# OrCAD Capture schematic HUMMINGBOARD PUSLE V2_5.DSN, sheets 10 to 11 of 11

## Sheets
10 MIPI-DSI to HDMI: size C; title: MIPI-DSI to HDMI; rev: 2.4.0
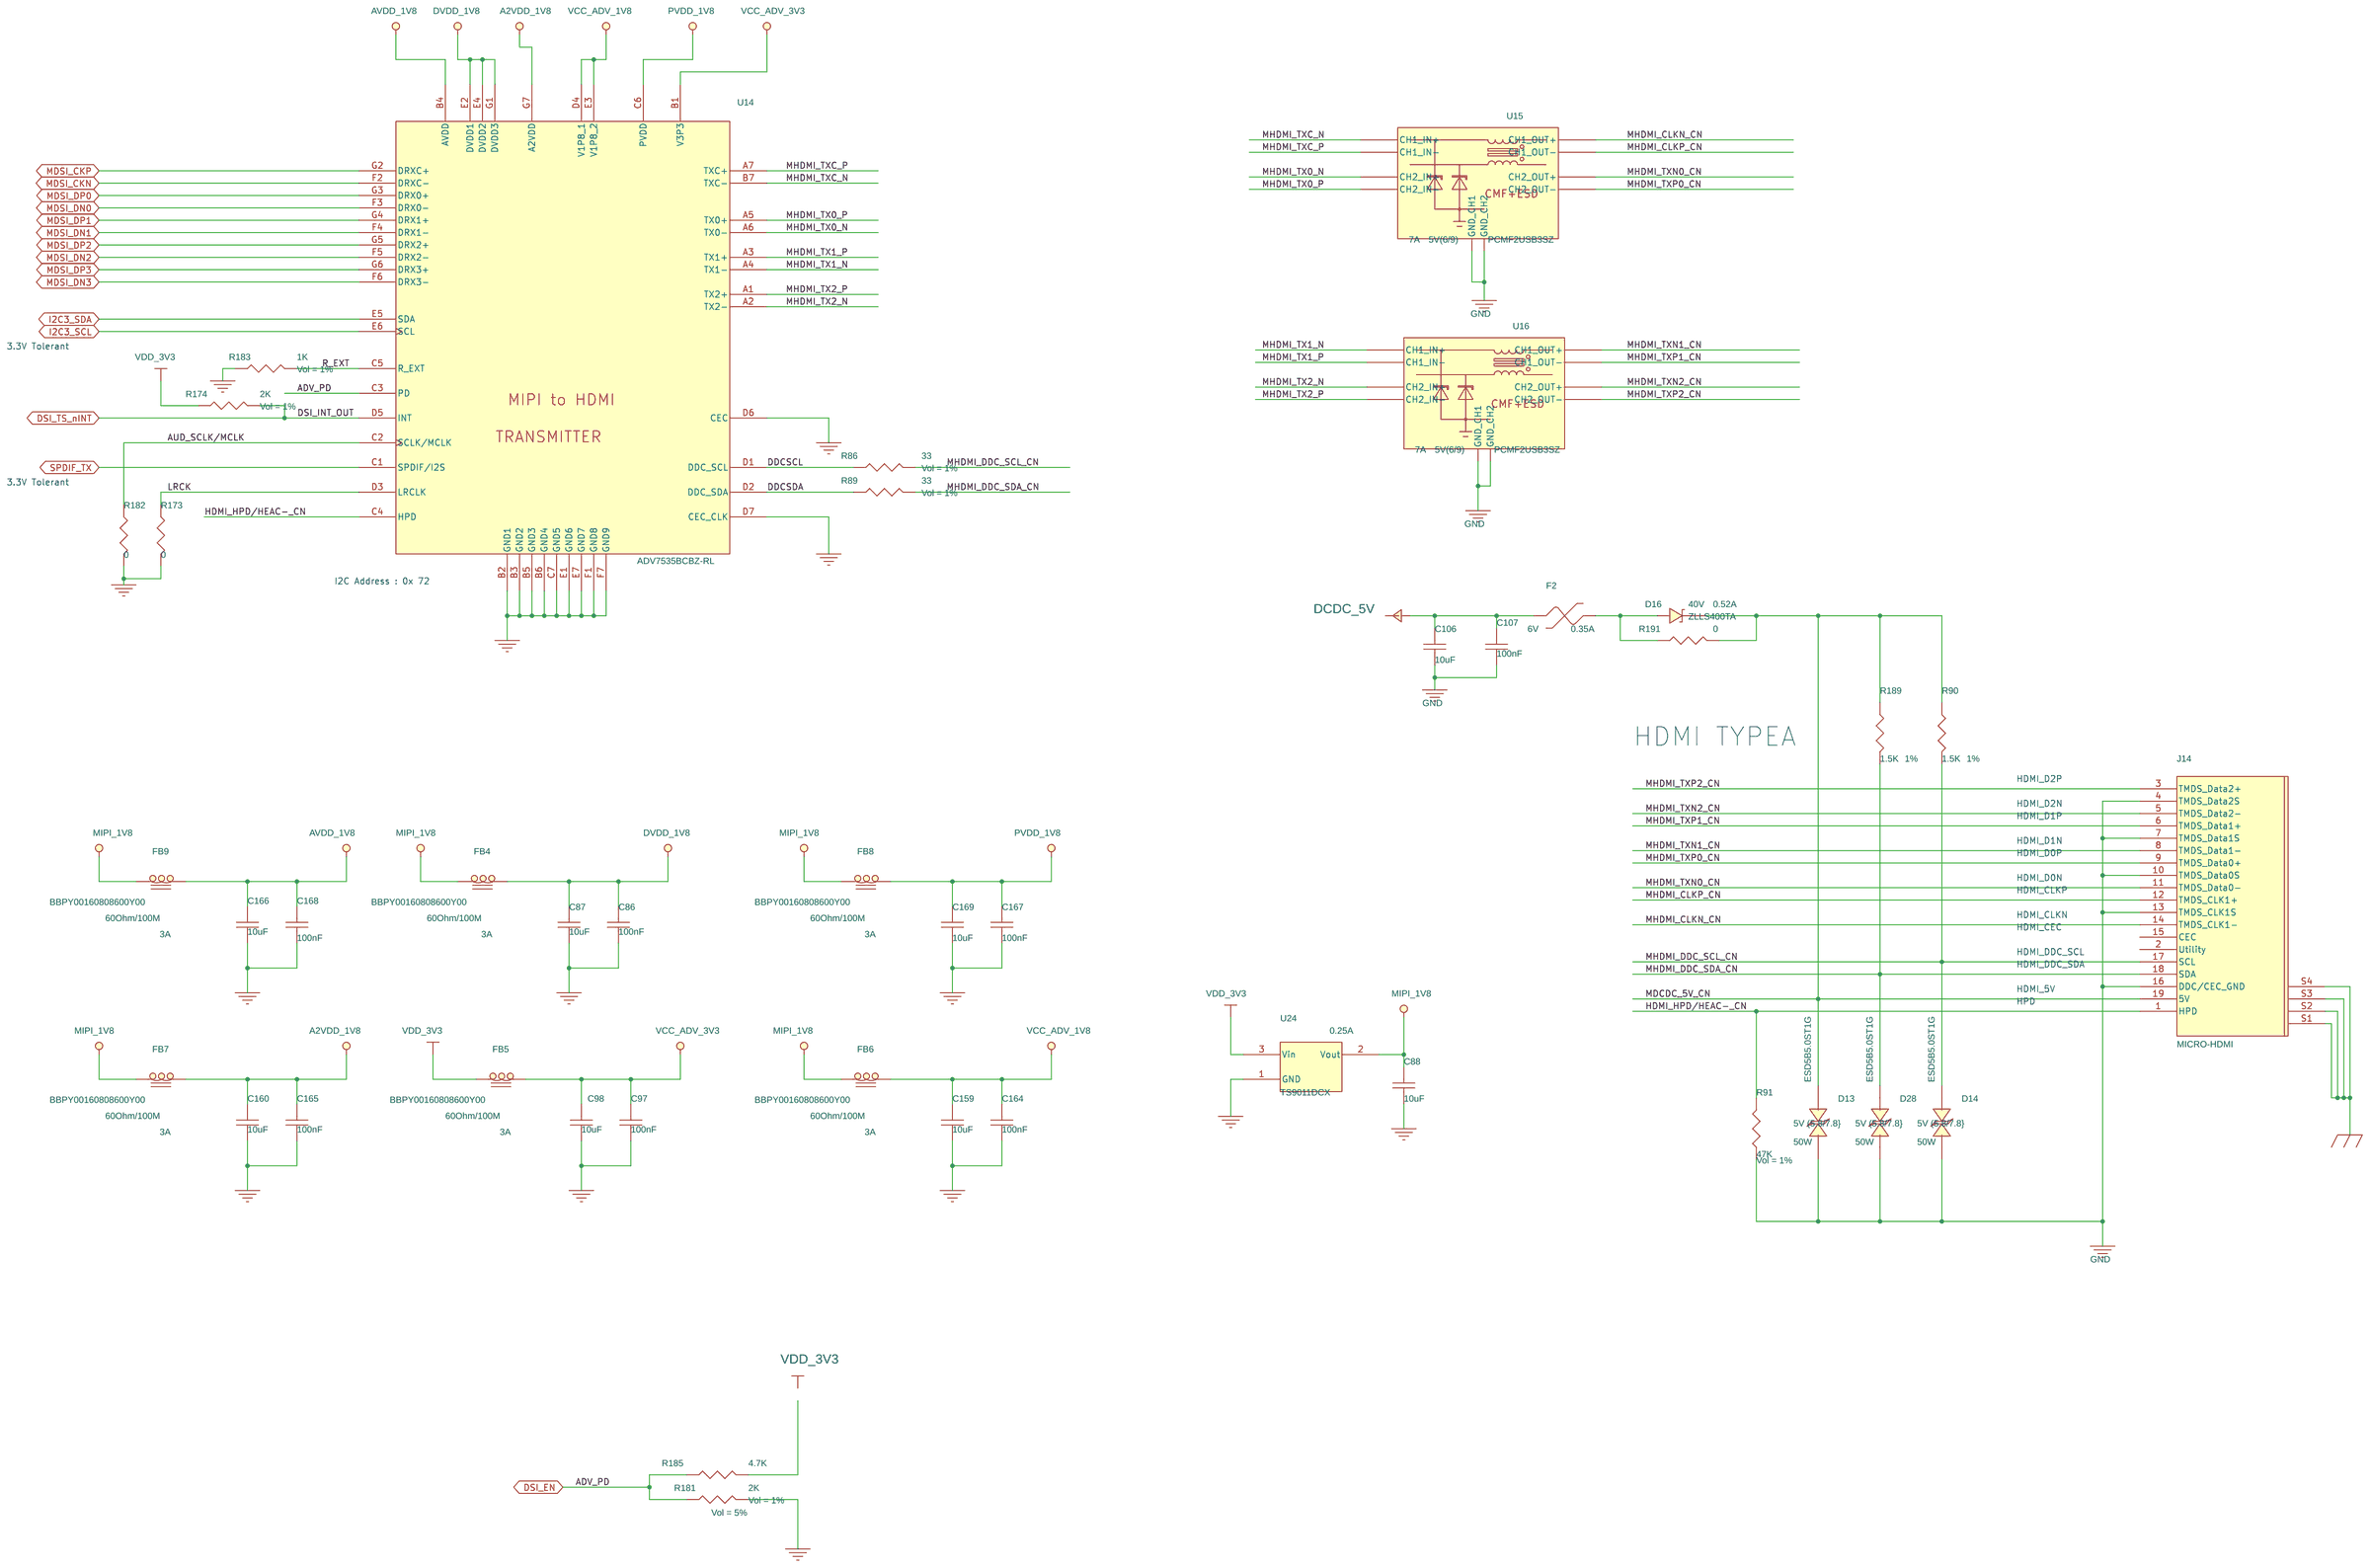
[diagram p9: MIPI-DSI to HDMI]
11 History: title: HISTORY
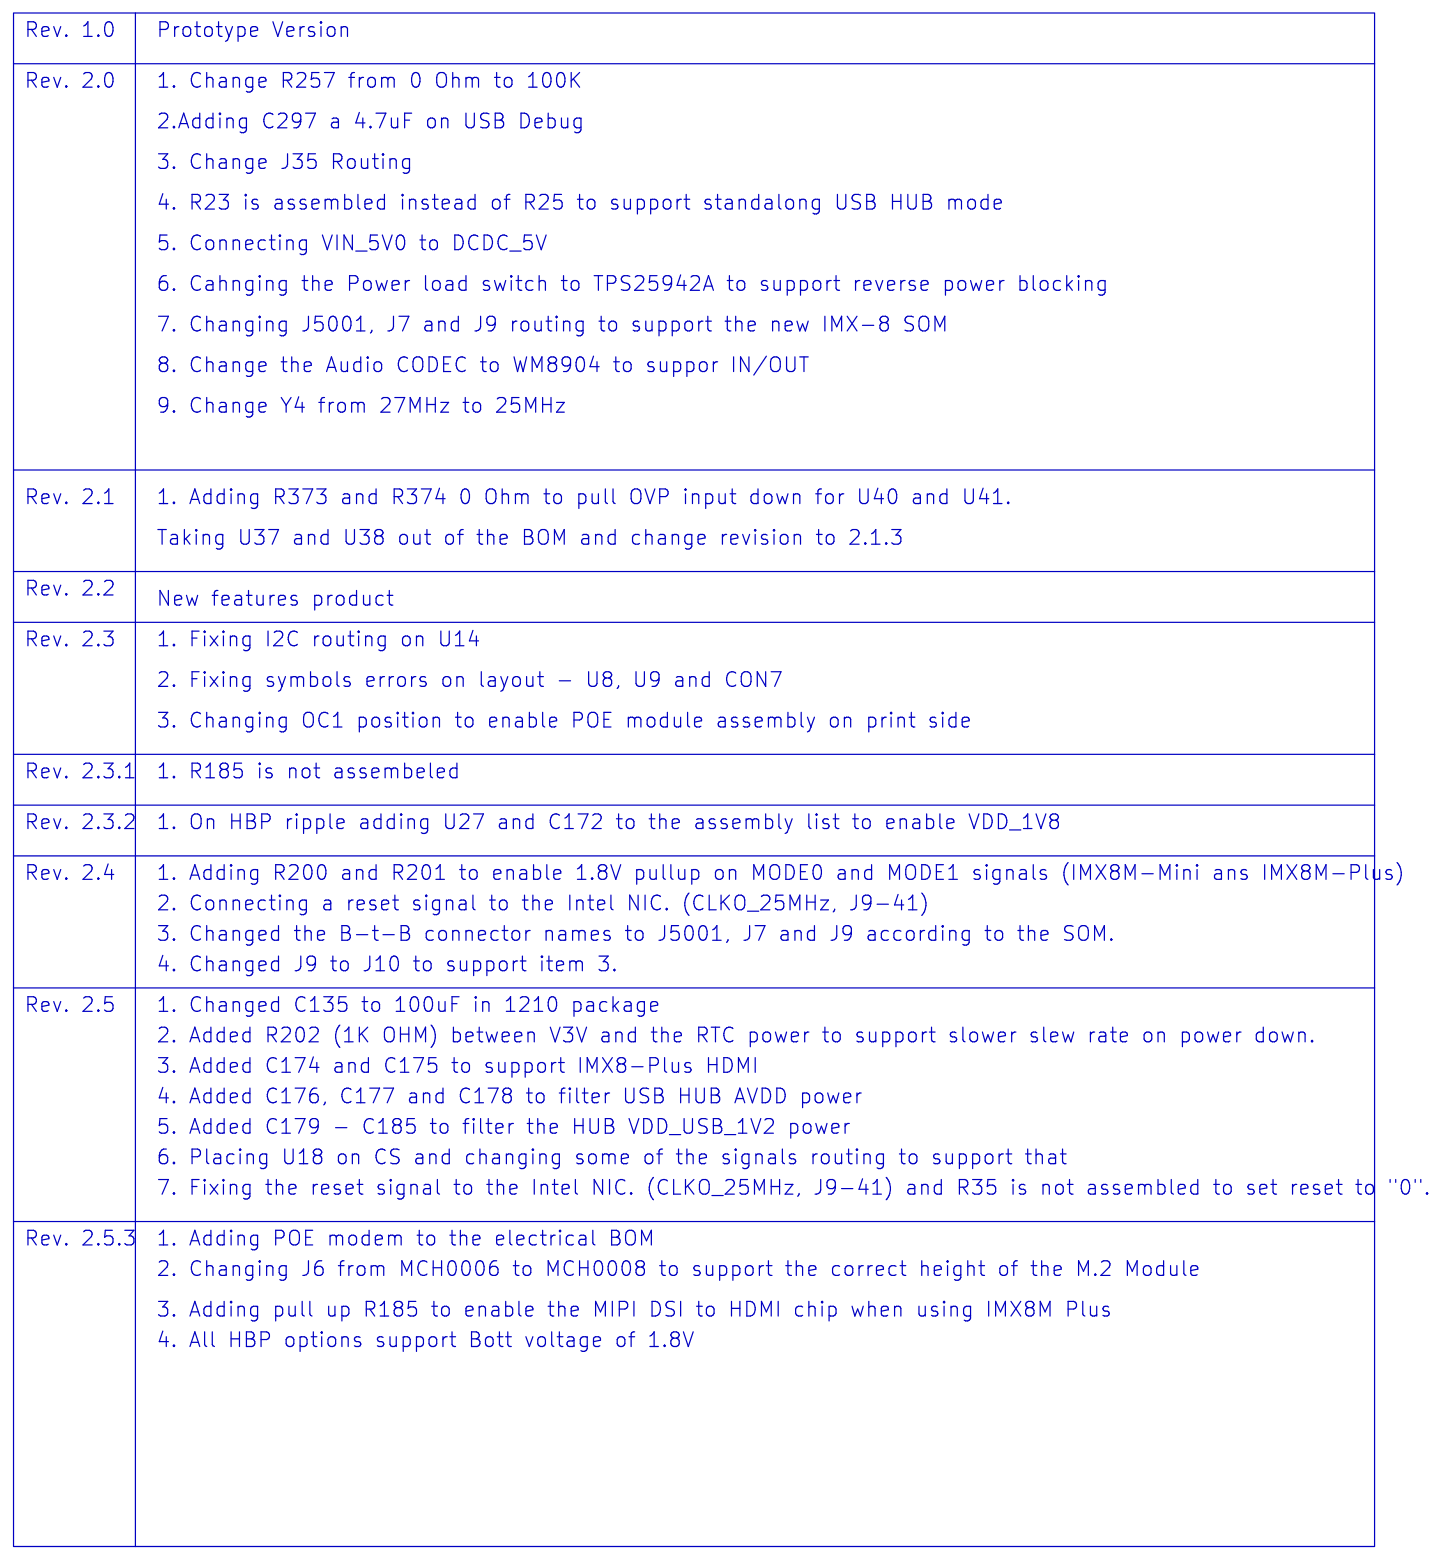
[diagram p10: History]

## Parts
C86  100nF  [C0402]
C87  10uF  [C0603]
C88  10uF  [C0603]
C97  100nF  [C0402]
C98  10uF  [C0603]
C106  10uF  [C0603]
C107  100nF  [C0402]
C159  10uF  [C0603]
C160  10uF  [C0603]
C164  100nF  [C0402]
C165  100nF  [C0402]
C166  10uF  [C0603]
C167  100nF  [C0402]
C168  100nF  [C0402]
C169  10uF  [C0603]
D13  ESD5B5.0ST1G  [ESD5B5.0ST1G]
D14  ESD5B5.0ST1G  [ESD5B5.0ST1G]
D16  ZLLS400TA  [ZLLS400TA]
D28  ESD5B5.0ST1G  [ESD5B5.0ST1G]
F2  6V  [PICOSMDC035S-2]
FB4  BBPY00160808600Y00  [BBPY00160808600Y00]
FB5  BBPY00160808600Y00  [BBPY00160808600Y00]
FB6  BBPY00160808600Y00  [BBPY00160808600Y00]
FB7  BBPY00160808600Y00  [BBPY00160808600Y00]
FB8  BBPY00160808600Y00  [BBPY00160808600Y00]
FB9  BBPY00160808600Y00  [BBPY00160808600Y00]
J14  MICRO-HDMI  [0467651001]
R86  33  [R0402]
R89  33  [R0402]
R90  1.5K  [R0402]
R91  47K  [R0402]
R173  0  [R0402]
R174  2K  [R0402]
R181  2K  [R0402]
R182  0  [R0402]
R183  1K  [R0402]
R185  4.7K  [R0402]
R189  1.5K  [R0402]
R191  0  [R0402]
U14  ADV7535BCBZ-RL  [ADV7535BCBZ-RL]
U15  PCMF2USB3SZ  [PCMF2USB3SZ]
U16  PCMF2USB3SZ  [PCMF2USB3SZ]
U24  TS9011DCX  [TS9011DCX]

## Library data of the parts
C86 C97 C164 C165 C167 C168 = CAP_NP1: CAP CER 0.1uF ±10% 16V X7R 0402; Category: Capacitors (Size: 0402); Digikey P/N: 1276-1001-1-ND; Manufacturer: Samsung Electro-Mechanics; Part Num#: CL05B104KO5NNNC; Rating: 16V; SolidRun P/N: CA20013; Vol: 10%
C87 C98 C106 C159 C160 C166 C169 = CAP_NP1: CAP CER 10uF ±10% 16V X5R 0603; Category: Capacitors (Size: 0603); Digikey P/N: 490-10728-2-ND; Manufacturer: Murata Electronics North America; Part Num#: GRM188R61C106KAALD; Rating: 16V; SolidRun P/N: CA30014; Vol: 10%
C88 = CAP_NP1: CAP CER 10uF ±10% 6.3V X5R 0603; Category : Capacitors (Size: 0603); Digikey P/N: 1276-1038-1-ND; Manufacturer: Samsung Electro-Mechanics; Part Num#: CL10A106KQ8NNNC; Rating: 6.3V; SolidRun P/N: CA30001; Vol: 10%
C107 = CAP_NP1: CAP CER 0.1uF ±10% 16V X7R 0402; Category: Capacitors (Size: 0402); Category : Capacitors (Size: 0402); Digikey P/N: 1276-1001-1-ND; Manufacturer: Samsung Electro-Mechanics; Part Num#: CL05B104KO5NNNC; Rating: 16V; SolidRun P/N: CA20013; Vol: 10%
D13 D14 D28 = TVS-BI: TVS DIODE 5VWM SOD523 BI; Category: DI-TVS; Category : DI-TVS; Digikey P/N: ESD5B5.0ST1GOSTR-ND; Manufacturer: ON Semiconductor; Rating: 50W; SolidRun P/N: DI00242; Vol: 5V (5.8/7.8}; Datasheet: http://www.onsemi.com/pub/Collateral/ESD5B5.0ST1-D.PDF
D16 = Diode-STK: DIODE SCHOTTKY 40V 520MA SOD323; Category: DI-Diode; Digikey P/N: ZLLS400TATR-ND; Manufacturer: Diodes Incorporated; Rating: 0.52A; SolidRun P/N: DI00234; Vol: 40V; Datasheet: https://www.diodes.com/assets/Datasheets/ZLLS400.pdf
F2 = FUSE_RESETTABLE: PTC RESET FUSE 6V 350MA 0805; Category: Fuse-PTC; Category : Fuse-PTC; Digikey P/N: PICOSMDC035S-2TR-ND; Manufacturer: Littelfuse Inc.; Rating: 0.35A; SolidRun P/N: FS00020; Datasheet: http://www.littelfuse.com/~/media/electronics/product_specifications/resettable_ptcs/littelfuse_ptc_picosmdc035s_2_product_specification.pdf.pdf
FB4-FB9 = Ferrite_Bead: Multilayer Ferrite Chip Beads 60 OHM 3A; Category: COILS-FERRIT; Manufacturer: Chilisin Electronics Corp; Rating: 3A; SolidRun P/N: IN00049; Vol: 60Ohm/100M; Datasheet: https://www.chilisin.com/upload/media/product/emi/file/BBPY_Series.pdf
J14 = J-Micro_HDMI_connector: HDMI - Micro  Receptacle Connector 19 Position Surface Mount, Right Angle; Through Hole; Category: CON-HDMI/DP; Digikey P/N: WM1282TR-ND; Manufacturer: Molex; SolidRun P/N: CO00747; Datasheet: https://www.molex.com/pdm_docs/sd/467651001_sd.pdf
R86 R89 = RES1: RES SMD 33 OHM 1% 1/16W 0402; Category: Resistors (Size: 0402); Digikey P/N: 311-33.0LRCT-ND; Manufacturer: YAGEO; Part Num#: RC0402FR-0733RL; Rating: 1/16W; SolidRun P/N: RE20502; Vol: 1%
R90 R189 = RES1: RES SMD 1.5K OHM 1% 1/16W 0402; Category: Resistors (Size: 0402); Category : Resistors (Size: 0402); Manufacturer: THYE MING; Part Num#: CR-02FL6---1K5; Rating: 1/16W; SolidRun P/N: RE20029; Vol: 1%
R91 = RES1: RES SMD 47K OHM 1% 1/16W 0402; Category: Resistors (Size: 0402); Digikey P/N: 311-47.0KLRCT-ND; Manufacturer: YAGEO; Part Num#: RC0402FR-0747KL; Rating: 1/16W; SolidRun P/N: RE20469; Vol: 1%
R173 R182 = RES1: RES SMD 0 OHM JUMPER 1/16W 0402; Category: Resistors (Size: 0402); Digikey P/N: 311-0.0JRCT-ND; Manufacturer: YAGEO; Part Num#: RC0402JR-070RL; Rating: 1/16W; SolidRun P/N: RE20009
R174 R181 = RES1: RES SMD 2K OHM 1% 1/10W 0402; Category: Resistors (Size: 0402); Digikey P/N: P2.00KLTR-ND; Manufacturer: Panasonic Electronic Components; Part Num#: ERJ-2RKF2001X; Rating: 1/10W; SolidRun P/N: RE20524; Vol: 1%
R183 = RES1: RES SMD 1K OHM 1% 1/16W 0402; Category: Resistors (Size: 0402); Digikey P/N: 311-1.00KLRCT-ND; Manufacturer: YAGEO; Part Num#: RC0402FR-071KL; Rating: 1/16W; SolidRun P/N: RE20500; Vol: 1%
R185 = RES1: RES SMD 4.7K OHM 5% 1/16W 0402; Category: Resistors (Size: 0402); Digikey P/N: 311-4.7KJRCT-ND; Manufacturer: YAGEO; Part Num#: RC0402JR-074K7L; Rating: 1/16W; SolidRun P/N: RE20002; Vol: 5%
R191 = RES1: RES SMD 0 OHM JUMPER 1/16W 0402; Category: Resistors (Size: 0402); Category : Resistors (Size: 0402); Digikey P/N: 311-0.0JRCT-ND; Manufacturer: YAGEO; Part Num#: RC0402JR-070RL; Rating: 1/16W; SolidRun P/N: RE20009
U14 = IC-ADV7535BCBZ: MIPI/DSI Receiver with HDMI Transmitter; Category: IC-HDMI/LVDS; Manufacturer: Analog Devices Inc.; SolidRun P/N: IC01367
U15 U16 = D-PCMF2USB3S: CMC 4LN SMD ESD USB 3.1, USB 2.0, HDMI 2.0, HDMI 1.4; Category: DI-TVS; Category : DI-TVS; Digikey P/N: 1727-2509-2-ND; Manufacturer: Nexperia USA Inc.; Rating: 7A; SolidRun P/N: DI00240; Vol: 5V(6/9); Datasheet: https://assets.nexperia.com/documents/data-sheet/PCMFXUSB3S_SER.pdf
U24 = IC-TS9011DCX: LDO - 1.8V output, 0.25A, 12V maximum in; Category : IC-PWR-LDO; Digikey P/N: TS9011DCXRFG-ND; Manufacturer: Taiwan Semiconductor Corporation; Rating: 0.25A; SolidRun P/N: IC00014; VOL: 1.8V; Datasheet: http://www.taiwansemi.com/products/datasheet/TS9011_H1608.pdf

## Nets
A2VDD_1V8: C160.1 C165.1 FB7.2 U14.G7(A2VDD)
AVDD_1V8: C166.1 C168.1 FB9.2 U14.B4(AVDD)
DVDD_1V8: C86.1 C87.1 FB4.2 U14.E2(DVDD1) U14.E4(DVDD2) U14.G1(DVDD3)
GND: C86.2 C87.2 C88.2 C97.2 C98.2 C106.2 C107.2 C159.2 C160.2 C164.2 C165.2 C166.2 C167.2 C168.2 C169.2 D13.1 D14.1 D28.1 J14.4(TMDS_Data2S) J14.7(TMDS_Data1S) J14.10(TMDS_Data0S) J14.13(TMDS_CLK1S) J14.16(DDC/CEC_GND) R91.2 R173.2 R181.2 R182.2 R183.1 U14.B2(GND1) U14.B3(GND2) U14.B5(GND3) U14.B6(GND4) U14.C7(GND5) U14.D6(CEC) U14.D7(CEC_CLK) U14.E1(GND6) U14.E7(GND7) U14.F1(GND8) U14.F7(GND9) U15.B1(GND_CH1) U15.B2(GND_CH2) U16.B1(GND_CH1) U16.B2(GND_CH2) U24.1(GND) ; also on sheet 1 2 3 4 5 6 7 8 9
GNDC: J14.S1 J14.S2 J14.S3 J14.S4 ; also on sheet 1 4 5 7 8
PVDD_1V8: C167.1 C169.1 FB8.2 U14.C6(PVDD)
VCC_ADV_1V8: C159.1 C164.1 FB6.2 U14.D4(V1P8_1) U14.E3(V1P8_2)
VCC_ADV_3V3: C97.1 C98.1 FB5.2 U14.B1(V3P3)
VDD_3V3: FB5.1 R174.1 R185.2 U24.3(Vin) ; also on sheet 2 3 4 5 6 7 8 9
AUD_SCLK/MCLK: R182.1 U14.C2(SCLK/MCLK)
DCDC_5V: C106.1 C107.1 F2.1 ; also on sheet 1 2 4 5 8 9
DDCSCL: R86.1 U14.D1(DDC_SCL)
DDCSDA: R89.1 U14.D2(DDC_SDA)
DSI_EN: R181.1 R185.1 U14.C3(PD) ; also on sheet 8 9
DSI_TS_nINT: R174.2 U14.D5(INT) ; also on sheet 8 9
HDMI_HPD/HEAC-_CN: J14.1(HPD) R91.1 U14.C4(HPD)
I2C3_SCL: U14.E6(SCL) ; also on sheet 2 3 7 8 9
I2C3_SDA: U14.E5(SDA) ; also on sheet 2 3 7 8 9
LRCK: R173.1 U14.D3(LRCLK)
MDCDC_5V_CN: D13.2 D16.C(CATHODE) J14.19(5V) R90.1 R189.1 R191.2
MDSI_CKN: U14.F2(DRXC-) ; also on sheet 8
MDSI_CKP: U14.G2(DRXC+) ; also on sheet 8
MDSI_DN0: U14.F3(DRX0-) ; also on sheet 8
MDSI_DN1: U14.F4(DRX1-) ; also on sheet 8
MDSI_DN2: U14.F5(DRX2-) ; also on sheet 8
MDSI_DN3: U14.F6(DRX3-) ; also on sheet 8
MDSI_DP0: U14.G3(DRX0+) ; also on sheet 8
MDSI_DP1: U14.G4(DRX1+) ; also on sheet 8
MDSI_DP2: U14.G5(DRX2+) ; also on sheet 8
MDSI_DP3: U14.G6(DRX3+) ; also on sheet 8
MHDMI_CLKN_CN: J14.14(TMDS_CLK1-) U15.C1(CH1_OUT+)
MHDMI_CLKP_CN: J14.12(TMDS_CLK1+) U15.C2(CH1_OUT-)
MHDMI_DDC_SCL_CN: D14.2 J14.17(SCL) R86.2 R90.2
MHDMI_DDC_SDA_CN: D28.2 J14.18(SDA) R89.2 R189.2
MHDMI_TX0_N: U14.A6(TX0-) U15.A3(CH2_IN+)
MHDMI_TX0_P: U14.A5(TX0+) U15.A4(CH2_IN-)
MHDMI_TX1_N: U14.A4(TX1-) U16.A1(CH1_IN+)
MHDMI_TX1_P: U14.A3(TX1+) U16.A2(CH1_IN-)
MHDMI_TX2_N: U14.A2(TX2-) U16.A3(CH2_IN+)
MHDMI_TX2_P: U14.A1(TX2+) U16.A4(CH2_IN-)
MHDMI_TXC_N: U14.B7(TXC-) U15.A1(CH1_IN+)
MHDMI_TXC_P: U14.A7(TXC+) U15.A2(CH1_IN-)
MHDMI_TXN0_CN: J14.11(TMDS_Data0-) U15.C3(CH2_OUT+)
MHDMI_TXN1_CN: J14.8(TMDS_Data1-) U16.C1(CH1_OUT+)
MHDMI_TXN2_CN: J14.5(TMDS_Data2-) U16.C3(CH2_OUT+)
MHDMI_TXP0_CN: J14.9(TMDS_Data0+) U15.C4(CH2_OUT-)
MHDMI_TXP1_CN: J14.6(TMDS_Data1+) U16.C2(CH1_OUT-)
MHDMI_TXP2_CN: J14.3(TMDS_Data2+) U16.C4(CH2_OUT-)
MIPI_1V8: C88.1 FB4.1 FB6.1 FB7.1 FB8.1 FB9.1 U24.2(Vout)
R_EXT: R183.2 U14.C5(R_EXT)
SPDIF_TX: U14.C1(SPDIF/I2S) ; also on sheet 8 9
N16533848: D16.A(ANODE) F2.2 R191.1

Not connected (* = marked no-connect by the designer): J14 2(Utility) 15(CEC)

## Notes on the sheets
sheet 10
- 3.3V Tolerant
- 3.3V Tolerant
- I2C Address : 0x 72
- HDMI TYPEA
- HDMI_D2P
- HDMI_D2N
- HDMI_D1P
- HDMI_D1N
- HDMI_D0P
- HDMI_D0N
- HDMI_CLKP
- HDMI_CLKN
- HDMI_CEC
- HDMI_DDC_SCL
- HDMI_DDC_SDA
- HDMI_5V
- HPD
sheet 11
- Rev. 1.0
- Prototype Version
- Rev. 2.0
- 1. Change R257 from 0 Ohm to 100K
- 2.Adding C297 a 4.7uF on USB Debug
- 3. Change J35 Routing
- 4. R23 is assembled instead of R25 to support standalong USB HUB mode
- 5. Connecting VIN_5V0 to DCDC_5V
- 6. Cahnging the Power load switch to TPS25942A to support reverse power blocking
- 7. Changing J5001, J7 and J9 routing to support the new IMX-8 SOM
- 8. Change the Audio CODEC to WM8904 to suppor IN/OUT
- 9. Change Y4 from 27MHz to 25MHz
- Rev. 2.1
- 1. Adding R373 and R374 0 Ohm to pull OVP input down for U40 and U41.
- Taking U37 and U38 out of the BOM and change revision to 2.1.3
- Rev. 2.2
- New features product
- Rev. 2.3
- 1. Fixing I2C routing on U14
- 2. Fixing symbols errors on layout - U8, U9 and CON7
- 3. Changing OC1 position to enable POE module assembly on print side
- Rev. 2.3.1
- 1. R185 is not assembeled
- Rev. 2.3.2
- 1. On HBP ripple adding U27 and C172 to the assembly list to enable VDD_1V8
- Rev. 2.4
- 1. Adding R200 and R201 to enable 1.8V pullup on MODE0 and MODE1 signals (IMX8M-Mini ans IMX8M-Plus)
- 2. Connecting a reset signal to the Intel NIC. (CLKO_25MHz, J9-41)
- 3. Changed the B-t-B connector names to J5001, J7 and J9 according to the SOM.
- 4. Changed J9 to J10 to support item 3.
- Rev. 2.5
- 1. Changed C135 to 100uF in 1210 package
- 2. Added R202 (1K OHM) between V3V and the RTC power to support slower slew rate on power down.
- 3. Added C174 and C175 to support IMX8-Plus HDMI
- 4. Added C176, C177 and C178 to filter USB HUB AVDD power
- 5. Added C179 - C185 to filter the HUB VDD_USB_1V2 power
- 6. Placing U18 on CS and changing some of the signals routing to support that
- 7. Fixing the reset signal to the Intel NIC. (CLKO_25MHz, J9-41) and R35 is not assembled to set reset to "0".
- Rev. 2.5.3
- 1. Adding POE modem to the electrical BOM
- 2. Changing J6 from MCH0006 to MCH0008 to support the correct height of the M.2 Module
- 3. Adding pull up R185 to enable the MIPI DSI to HDMI chip when using IMX8M Plus
- 4. All HBP options support Bott voltage of 1.8V
